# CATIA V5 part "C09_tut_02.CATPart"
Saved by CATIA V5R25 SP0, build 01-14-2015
Part number: Part1
Bounding box of the stored display mesh (mm): x -258 to 0, y -74.587 to 74.587, z -81.796 to 81.796
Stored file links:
  E:\ashutosh\Academics\Catia\CATIA V5-6R2013_partfiles\Tutorials_ver_2\C09_tut_02.CATPart
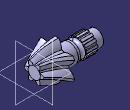
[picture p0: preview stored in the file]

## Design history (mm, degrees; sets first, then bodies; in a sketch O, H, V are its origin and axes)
Body1 (main body)
  Sketch1 on zx-plane, origin (0, 0, 0), H (-1, 0, 0), V (0, 0, 1)
    line L1 (0, 0) -> (258, 0)
    line L2 (258, 0) -> (258, -32.5)
    line L3 (0, 0) -> (0, -25)
    line L4 (0, -25) -> (95, -50)
    point P4 (95, -50)
    point P5 (95, -50)
    line L5 (95, -50) -> (95, -45)
    line L6 (95, -45) -> (100, -45)
    line L7 (100, -45) -> (100, -39)
    line L8 (100, -39) -> (146, -39)
    line L9 (258, -32.5) -> (226, -32.5)
    line L10 (226, -32.5) -> (226, -36)
    line L11 (226, -36) -> (178, -36)
    arc A1 centre (167, -36) radius 11 from (178, -36) to (156, -36) ccw
    point P13 (167, -36)
    line L12 (146, -39) -> (146, -38)
    line L13 (146, -38) -> (156, -38)
    line L14 (156, -38) -> (156, -36)
    point P16 (156, -36)
    point P17 (156, -36)
    axis line L15 (258, 0) -> (-34.5416, 0)
    length L1 = 258
    length L2 = 32.5
    length L3 = 25
    distance P4 L3 = 95
    length L5 = 5
    length L6 = 5
    distance L6 L1 = 45
    length L9 = 32
    length L10 = 3.5
    radius A1 = 11
    length L12 = 1
    length L13 = 10
    length L14 = 2
    distance L13 L1 = 38
    length L11 = 48
    horizontal: L1 H, L6 H, L8 H, L9 H, L11 H, L13 H, L15 H
    vertical: L2 V, L3 V, L5 V, L7 V, L10 V, L12 V, L14 V
    coincidence: P5 P4, P13 L11, P16 P17
  Shaft1: profile Sketch1, axis Sketch1.L15, angle 360
  Sketch2 on face of Shaft1 from Sketch1.L10, origin (-226, 0, 0), H (0, -1, 0), V (0, 0, 1)
    line L1 (-5, 40.6511) -> (5, 40.6511)
    line L2 (5, 40.6511) -> (5, 35.6511)
    line L3 (-5, 35.6511) -> (-5, 40.6511)
    point P3 (5, 35.6511)
    point P4 (-5, 35.6511)
    reference projected circle E1 centre (0, 0) radius 36 from edge [face of Shaft1 from Sketch1.L10 | face of Shaft1 from Sketch1.L11]
    reference projected circle E2 centre (0, 0) radius 36 from edge [face of Shaft1 from Sketch1.L10 | face of Shaft1 from Sketch1.L11]
    point P5 (0, 35.9986)
    point P6 (12.0414, 33.9264)
    arc A1 centre (0, 0) radius 36 from (5, 35.6511) to (-5, 35.6511) ccw
    length L3 = 5
    length L1 = 10
    distance L2 V = 5
    horizontal: L1 H
    vertical: L2 V, L3 V
    coincidence: P3 E1, P4 E2, P5 V
  Pad1: profile Sketch2, direction (1, 0, 0), length 48
  CircPattern1: of Pad1, instances 13, angular step 27.6923 {= 360.0*1 deg/CircPattern1.AngularNumber}, axis from face of Shaft1 from Sketch1.L9
  Plane1: type Offset, RefPlane face of Shaft1 from Sketch1.L2, Offset 163
  Sketch3 on Plane1, origin (-95, 0, 0), H (0, 1, 0), V (0, 0, 1)
    projected circle E1 centre (0, 0) radius 50 from edge [face of Shaft1 from Sketch1.L5 | face of Shaft1 from Sketch1.L4]
    projected arc E2 centre (0, 0) radius 50 from (20, 45.8258) to (-20, 45.8258) ccw from edge [face of Shaft1 from Sketch1.L5 | face of Shaft1 from Sketch1.L4]
    arc A1 centre (44.9551, 43.4104) radius 65 from (-20, 45.8258) to (-7.5, 81.7961) cw
    point P2 (-20, 45.8258)
    point P3 (-7.5, 81.7961)
    point P4 (20, 45.8258)
    point P5 (7.5, 81.7961)
    arc A2 centre (-44.9551, 43.4104) radius 65 from (20, 45.8258) to (7.5, 81.7961) ccw
    line L1 (-7.5, 81.7961) -> (7.5, 81.7961)
    radius A1 = 65
    length L1 = 15
    distance P2 P4 = 40
    coincidence: P2 E1
    symmetry: P2 P4 V, P3 P5 V, A1 A2 V
    horizontal: L1 H
  Plane2: type Offset, RefPlane face of Shaft1 from Sketch1.L2, Offset 210
  Sketch4 on Plane2, origin (-48, 0, 0), H (0, 1, 0), V (0, 0, 1)
    arc A1 centre (0, 0) radius 37.5 from (5.5935, 37.0805) to (-23.3843, 29.3159) ccw
    point P1 (5.5935, 37.0805)
    point P2 (-23.3843, 29.3159)
    arc A2 centre (-40.9945, 22.7216) radius 48.7506 from (5.5935, 37.0805) to (-10.4445, 60.7126) ccw
    point P3 (-10.4445, 60.7126)
    line L1 (-10.4445, 60.7126) -> (-21.3111, 57.8008)
    point P4 (-21.3111, 57.8008)
    arc A3 centre (24.1415, 40.1748) radius 48.7506 from (-21.3111, 57.8008) to (-23.3843, 29.3159) ccw
    reference projected circle E1 centre (0, 0) radius 25 from edge [face of Shaft1 from Sketch1.L4 | face of Shaft1 from Sketch1.L3]
    length L1 = 11.25
    radius A3 = 48.7506
    radius A1 = 37.5
    angle L1 H = 15
    radius A2 = 48.7506
    distance P1 V = 5.5935
    distance P2 V = 23.3843
    distance P3 V = 10.4445
    distance P4 H = 57.8008
    concentricity: A1 E1
  Sketch5 on face of Shaft1 from Sketch1.L3, origin (0, 0, 0), H (0, 1, 0), V (0, 0, 1)
    arc A1 centre (0, 0) radius 25 from (-2.7962, 24.8431) to (-20.1167, 14.8431) ccw
    arc A2 centre (-30.319, 7.5582) radius 32.5004 from (-2.7962, 24.8431) to (-17.2014, 37.2937) ccw
    line L1 (-17.2014, 37.2937) -> (-23.6966, 33.5437)
    arc A3 centre (8.6139, 30.0361) radius 32.5004 from (-23.6966, 33.5437) to (-20.1167, 14.8431) ccw
  Loft1: solid, Sections (Sketch3; Sketch4; Sketch5)
  CircPattern2: of Loft1, instances 6, angular step 60 {= 360.0*1 deg/CircPattern2.AngularNumber}, axis from face of Shaft1 from Sketch1.L4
